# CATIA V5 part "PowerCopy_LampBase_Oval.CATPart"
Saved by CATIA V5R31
Part number: LampBase_Oval
Bounding box of the stored display mesh (mm): x -75 to 75, y -75 to 75, z 0 to 20
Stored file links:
  C:\Users\patol451\OneDrive - Linköpings universitet\Nuvarande kurser\Exjobb\LampCATIA\PowerCopy_LampBase_Oval.CATPart
  C:\Users\patol451\OneDrive - Linköpings universitet\Nuvarande kurser\Exjobb\LampCATIA\LampReference.CATPart
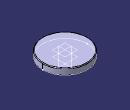
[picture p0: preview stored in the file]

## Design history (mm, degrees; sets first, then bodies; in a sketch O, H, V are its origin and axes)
Parameters
  baseDepth = 150 mm
  baseWidth = 150 mm
  baseHeight = 20 mm
  radius = 2 mm
Set1 "Reference Support"
  Point1: type OnPlane, Support xy-plane, H 0, V 75 {= baseDepth /2}, Direction (1, 0, 0)
  Point2 "Point.2": type OnPlane, Support xy-plane, H 75 {= baseWidth /2}, V 0, Direction (1, 0, 0)
  Symmetry1: Reference yz-plane, ToTransfor Point2
  Symmetry2: Reference zx-plane, ToTransfor Point1
Set2 "References"
  Curve1 "BaseEllipse": Elements (Symmetry1; Point1; Point2; Symmetry2), SemiClosure Point2
  Plane1 "BaseHeightPlane": type Offset, RefPlane xy-plane, Offset 20 {= baseHeight}
Set3 "Output"
  Point3 "OutputPoint1": type OnPlane, Support Plane1, H 0, V 0, Direction (1, 0, 0)
Set4 "PlacementSupport"
  Plane2: type 1Curve, Element1 Curve1
Set5 "Placement"
  Project1 "PlacementPoint": ToProject Point3, Support Plane2
Body1 (main body)
  Pad1 "BasePad": profile Curve1, up to Plane1
  Fillet1: radius 2 {= radius}, on end face of Pad1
